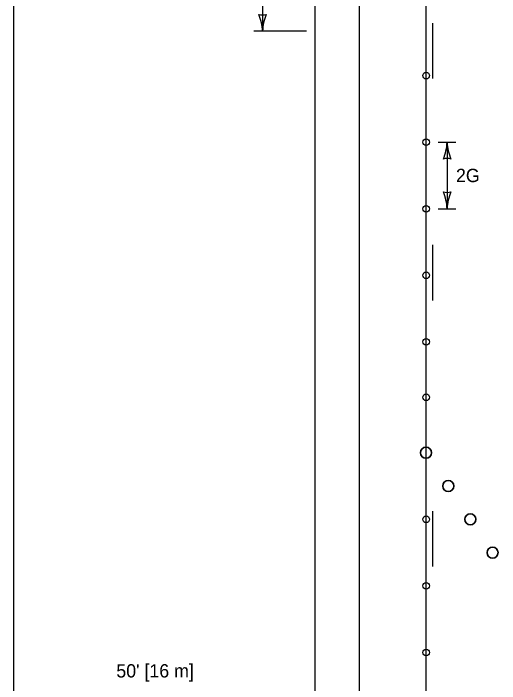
# Model space of a CAD drawing. Extents: x 49991.4 to 50021, y 49987.6 to 50011.4.
# Drawn here: x 50000.336 to 50002.53, y 50003.136 to 50006.157 of the extents above; entities that cross this region are included whole.
import ezdxf

# ---------------------------------------------------------------- set-up
doc = ezdxf.new("R2010")
doc.units = 0
for name, color, linetype in [('Level 1', 7, 'Continuous'), ('Level 2', 7, 'Continuous'), ('Level 3', 7, 'Continuous')]:
    doc.layers.add(name, color=color, linetype=linetype)

msp = doc.modelspace()

# ---------------------------------------------------------------- linework, layer by layer
at = {"layer": 'Level 1'}
for p, q in [((50001.6979, 50000.4631), (50001.6979, 50008.7736)), ((50001.8979, 50000.4631), (50001.8979, 50008.7736)), ((50002.1979, 50000.4631), (50002.1979, 50008.7736)), ((50002.2279, 50005.8631), (50002.2279, 50006.1131)), ((50002.2279, 50004.8631), (50002.2279, 50005.1131)), ((50002.2279, 50003.6631), (50002.2279, 50003.9131))]:
    msp.add_line(p, q, dxfattribs=at)
msp.add_lwpolyline([(50008.6146, 50011.2628), (50000.3356, 50011.2628), (50000.3356, 50000.0624), (50008.6146, 50000.0624)], close=True, dxfattribs=at)
for centre, radius in [((50002.1979, 50005.876), 0.015), ((50002.1979, 50005.576), 0.015), ((50002.1979, 50005.276), 0.015), ((50002.1979, 50004.976), 0.015), ((50002.1979, 50004.676), 0.015), ((50002.1979, 50004.426), 0.015), ((50002.1979, 50004.176), 0.025), ((50002.2979, 50004.026), 0.025), ((50002.1979, 50003.876), 0.015), ((50002.3979, 50003.876), 0.025), ((50002.4979, 50003.726), 0.025), ((50002.1979, 50003.576), 0.015), ((50002.1979, 50003.576), 0.015), ((50002.1979, 50003.276), 0.015)]:
    msp.add_circle(centre, radius, dxfattribs=at)
for centre, start, end in [((50002.1979, 50004.176), 0, 180), ((50002.1979, 50004.176), 180, 0), ((50002.2979, 50004.026), 0, 180), ((50002.2979, 50004.026), 180, 0), ((50002.3979, 50003.876), 0, 180), ((50002.3979, 50003.876), 180, 0), ((50002.4979, 50003.726), 0, 180), ((50002.4979, 50003.726), 180, 0)]:
    msp.add_arc(centre, 0.025, start, end, dxfattribs=at)
at = {"layer": 'Level 3'}
for p, q in [((50001.4599, 50006.676), (50001.4599, 50006.076)), ((50001.6579, 50006.076), (50001.4199, 50006.076)), ((50002.2529, 50005.576), (50002.3329, 50005.576)), ((50002.2929, 50005.576), (50002.2929, 50005.276)), ((50002.2529, 50005.276), (50002.3329, 50005.276))]:
    msp.add_line(p, q, dxfattribs=at)
for centre, radius, start, end in [((50001.4599, 50006.2042), 0.0548, 252.1388, 287.8612), ((50001.2271, 50006.0645), 0.233, 2.8273, 22.0772), ((50001.682, 50006.0668), 0.2223, 157.456, 177.6395), ((50002.0707, 50005.5852), 0.2223, 337.456, 357.6395), ((50002.5256, 50005.5875), 0.233, 182.8273, 202.0772), ((50002.2929, 50005.4478), 0.0548, 72.1388, 107.8612), ((50002.2929, 50005.4042), 0.0548, 252.1388, 287.8612), ((50002.0601, 50005.2645), 0.233, 2.8273, 22.0772), ((50002.515, 50005.2668), 0.2223, 157.456, 177.6395)]:
    msp.add_arc(centre, radius, start, end, dxfattribs=at)

# ---------------------------------------------------------------- texts
at = {"layer": 'Level 2'}
for s, p in [('2G', (50002.3329, 50005.396)), ("50' [16 m]", (50000.8002, 50003.163))]:
    msp.add_text(s, height=0.06, dxfattribs=at).set_placement(p)

doc.saveas('drawing.dxf')
